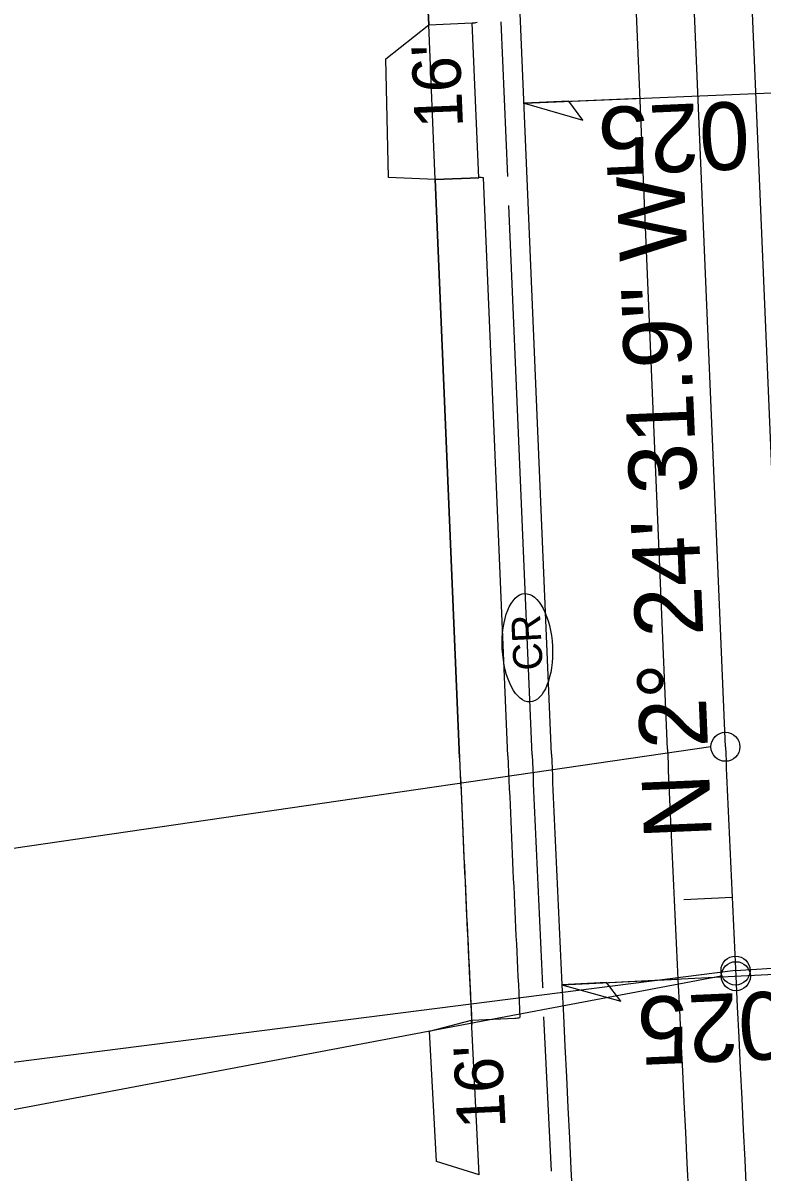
# Model space of a CAD drawing. Extents: x 2367848 to 2369479, y 800728 to 808616.
# Drawn here: x 2368770.1 to 2368846.5, y 803599.8 to 803718.6 of the extents above; entities that cross this region are included whole.
import ezdxf

# ---------------------------------------------------------------- set-up
doc = ezdxf.new("R2010")
doc.units = 0
for name, color, linetype in [('Prop Conc 2ft 6in Curb and Gutter', 7, 'Continuous'), ('Prop Conc 4in Sidewalk', 7, 'Continuous'), ('Prop Conc Drive Radius Type', 7, 'Continuous'), ('Prop Conc Driveway', 7, 'Continuous'), ('Prop Dimension', 7, 'Continuous'), ('Prop EOT', 7, 'Continuous'), ('Prop Horizontal Alignment', 7, 'Continuous'), ('Prop Horizontal Alignment Direction Label', 7, 'Continuous'), ('Prop Horizontal Alignment Station Label', 7, 'Continuous'), ('Prop Horizontal Alignment Tick Small', 7, 'Continuous'), ('Prop Lane Lines', 7, 'Continuous'), ('Prop Shade Light', 7, 'Continuous'), ('Prop Superelevation  Arrow CELL', 7, 'Continuous'), ('Prop Superelevation Label', 7, 'Continuous'), ('Prop WCC CELL', 7, 'Continuous'), ('Prop WCR CELL', 7, 'Continuous')]:
    doc.layers.add(name, color=color, linetype=linetype)

# ---------------------------------------------------------------- blocks, each defined once
blk = doc.blocks.new('CR')
at = {"layer": 'Prop WCC CELL'}
blk.add_ellipse((0.02, -0.02), major_axis=(5.61, 0), ratio=0.462467, dxfattribs=at)
blk.add_text('CR', height=3, dxfattribs=at).set_placement((-2.34, -1.5))

msp = doc.modelspace()

# ---------------------------------------------------------------- linework, layer by layer
at = {"layer": 'Prop Conc 2ft 6in Curb and Gutter'}
msp.add_line((2368822.78, 803642.92), (2368820.39, 803699.72), dxfattribs=at)
for centre, radius, start, end in [((2372339.67, 803790.87), 3520, 182.40885, 182.79745), ((2677047.33, 818679.94), 308591.21, 182.7974457, 182.7974859)]:
    msp.add_arc(centre, radius, start, end, dxfattribs=at)
at = {"layer": 'Prop Conc 4in Sidewalk'}
for p, q in [((2368812.1, 803718.39), (2368811.45, 803733.87)), ((2368815.29, 803642.61), (2368812.77, 803702.4)), ((2368820.28, 803642.82), (2368817.77, 803702.57))]:
    msp.add_line(p, q, dxfattribs=at)
for centre, radius, start, end in [((2368816.46, 803721.59), 3.01, 272.6175, 282.1749), ((2368817.39, 803699.6), 3, 82.8149, 92.4089), ((2372339.67, 803790.87), 3527.5, 182.40885, 182.85708), ((2372339.67, 803790.87), 3522.5, 182.40885, 182.84906), ((2368820.86, 803618.72), 3.02, 272.8619, 282.672)]:
    msp.add_arc(centre, radius, start, end, dxfattribs=at)
at = {"layer": 'Prop Conc Drive Radius Type'}
for p, q in [((2368820.27, 803702.72), (2368819.59, 803718.71)), ((2368824.8, 803599.88), (2368824.01, 803615.86))]:
    msp.add_line(p, q, dxfattribs=at)
at = {"layer": 'Prop Conc Driveway'}
for p, q in [((2368807.66, 803714.86), (2368812.1, 803718.39)), ((2368812.1, 803718.39), (2368816.6, 803718.58)), ((2368812.77, 803702.41), (2368812.1, 803718.39)), ((2368817.27, 803702.59), (2368816.6, 803718.58)), ((2368807.94, 803702.62), (2368807.66, 803714.86)), ((2368812.77, 803702.41), (2368807.94, 803702.62)), ((2368812.77, 803702.41), (2368817.27, 803702.59)), ((2368816.52, 803615.49), (2368821.01, 803615.71)), ((2368817.31, 803599.51), (2368816.52, 803615.49))]:
    msp.add_line(p, q, dxfattribs=at)
at = {"layer": 'Prop EOT'}
for p, q in [((2368824.78, 803643.01), (2368820.94, 803734.27)), ((2368812.16, 803614.38), (2368816.52, 803615.49)), ((2368812.89, 803600.9), (2368812.16, 803614.38)), ((2368817.31, 803599.51), (2368812.89, 803600.9))]:
    msp.add_line(p, q, dxfattribs=at)
for centre, radius, start, end in [((2372339.67, 803790.87), 3518, 182.40885, 182.79745), ((2677047.33, 818679.94), 308589.21, 182.7974457, 182.8728926)]:
    msp.add_arc(centre, radius, start, end, dxfattribs=at)
at = {"layer": 'Prop Horizontal Alignment'}
for p, q in [((2368842.76, 803643.76), (2368838.92, 803735.03)), ((2368843.81, 803620.63), (2369108.85, 803638.71))]:
    msp.add_line(p, q, dxfattribs=at)
for centre, radius, start, end in [((2372339.67, 803790.87), 3500, 182.40885, 182.79745), ((2677047.33, 818679.94), 308571.21, 182.7974457, 182.8728926)]:
    msp.add_arc(centre, radius, start, end, dxfattribs=at)
at = {"layer": 'Prop Horizontal Alignment Station Label'}
for p, q in [((2368841.26, 803643.76), (2368611.17, 803610.26)), ((2368843.81, 803620.63), (2368557.52, 803584.23)), ((2368842.34, 803620.05), (2368529.29, 803560.99))]:
    msp.add_line(p, q, dxfattribs=at)
for centre in [(2368842.76, 803643.76), (2368842.76, 803643.76), (2368843.81, 803620.63), (2368843.84, 803620.05), (2368843.84, 803620.05)]:
    msp.add_circle(centre, 1.5, dxfattribs=at)
at = {"layer": 'Prop Horizontal Alignment Tick Small'}
msp.add_line((2368843.45, 803628.17), (2368838.46, 803627.94), dxfattribs=at)
msp.add_line((2368843.45, 803628.17), (2368838.46, 803627.94), dxfattribs=at)
at = {"layer": 'Prop Lane Lines'}
for p, q in [((2368836.77, 803643.51), (2368832.93, 803734.77)), ((2368848.76, 803644.01), (2368844.92, 803735.28))]:
    msp.add_line(p, q, dxfattribs=at)
for centre, radius, start, end in [((2372339.67, 803790.87), 3506, 182.40885, 182.79745), ((2677047.33, 818679.94), 308577.21, 182.7974457, 182.8728926)]:
    msp.add_arc(centre, radius, start, end, dxfattribs=at)
at = {"layer": 'Prop Shade Light'}
for p, q in [((2368811.45, 803733.87), (2368812.1, 803718.39)), ((2368812.1, 803718.39), (2368816.6, 803718.58)), ((2368817.27, 803702.59), (2368812.77, 803702.41)), ((2368812.77, 803702.41), (2368815.29, 803642.61)), ((2368820.28, 803642.82), (2368817.77, 803702.57)), ((2368816.53, 803615.49), (2368821.01, 803615.71))]:
    msp.add_line(p, q, dxfattribs=at)
for centre, radius, start, end in [((2368816.46, 803721.59), 3.01, 272.6175, 282.1749), ((2368817.39, 803699.6), 3, 82.8149, 92.4089), ((2372339.67, 803790.87), 3527.5, 182.40885, 182.84977), ((2372339.67, 803790.87), 3522.5, 182.40885, 182.84906), ((2368820.86, 803618.72), 3.02, 272.8619, 282.672)]:
    msp.add_arc(centre, radius, start, end, dxfattribs=at)
at = {"layer": 'Prop Superelevation  Arrow CELL'}
for p, q in [((2368821.95, 803710.3), (2368833.94, 803710.8)), ((2368825.86, 803619.17), (2368837.85, 803619.75))]:
    msp.add_line(p, q, dxfattribs=at)
for points in [[(2368821.95, 803710.3), (2368828.03, 803708.55), (2368826.57, 803710.49)], [(2368825.86, 803619.17), (2368831.95, 803617.46), (2368830.48, 803619.39)]]:
    msp.add_lwpolyline(points, close=True, dxfattribs=at)
at = {"layer": 'Prop Superelevation Label'}
for p, q in [((2368821.95, 803710.3), (2368857.92, 803711.81)), ((2368825.86, 803619.17), (2368861.82, 803620.93))]:
    msp.add_line(p, q, dxfattribs=at)

# ---------------------------------------------------------------- block references
at = {"layer": 'Prop WCR CELL', "rotation": 92.86625998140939}
msp.add_blockref('CR', (2368822.27, 803653.98), dxfattribs=at)

# ---------------------------------------------------------------- texts
at = {"layer": 'Prop Dimension'}
for rotation, p in [(92.4089, (2368815.65, 803707.8)), (92.8001, (2368820.05, 803604.38))]:
    msp.add_text("16'", height=5, rotation=rotation, dxfattribs=at).set_placement(p)
at = {"layer": 'Prop Horizontal Alignment Direction Label'}
msp.add_text('N 2%%d 24\' 31.9" W', height=7, rotation=92.4089, dxfattribs=at).set_placement((2368841.36, 803634.36))
at = {"layer": 'Prop Superelevation Label'}
for p in [(2368845.1, 803710.5), (2368849.14, 803618.53)]:
    msp.add_text('025', height=7, rotation=182.4693, dxfattribs=at).set_placement(p)

doc.saveas('drawing.dxf')
